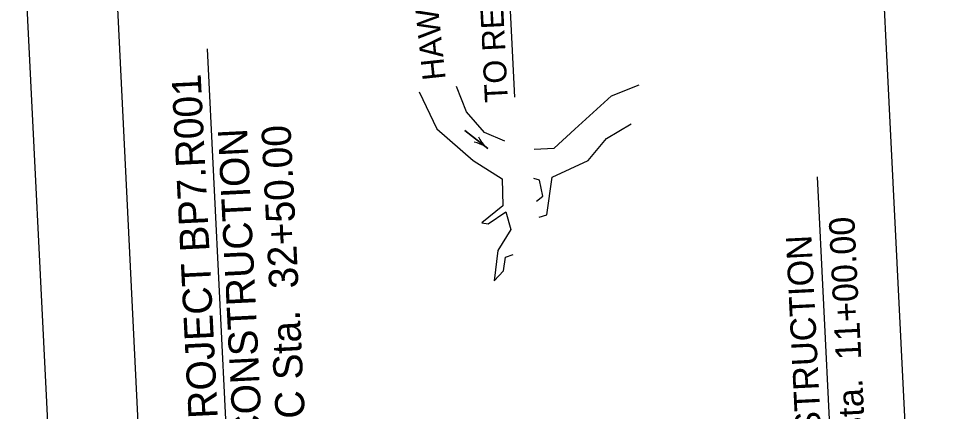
# Model space of a CAD drawing. Extents: x 1805231 to 1809482, y 908883 to 918297.
# Drawn here: x 1807021 to 1808278, y 915762 to 916301 of the extents above; entities that cross this region are included whole.
import ezdxf

# ---------------------------------------------------------------- set-up
doc = ezdxf.new("R2010")
doc.units = 0
for name, color, linetype in [('Default', 7, 'Continuous'), ('Prop Horizontal Alignment Station Label', 7, 'Continuous'), ('Prop Leader Line Medium', 7, 'Continuous'), ('Prop Shade Medium', 7, 'Continuous'), ('Scratch_Level_0', 7, 'Continuous')]:
    doc.layers.add(name, color=color, linetype=linetype)

msp = doc.modelspace()

# ---------------------------------------------------------------- linework, layer by layer
at = {"layer": 'Default'}
for p, q in [((1807833.8, 916195.4), (1807871.6, 916210.3)), ((1807570, 916200.9), (1807594.2, 916150.1)), ((1807635.2, 916173.4), (1807621.5, 916208.2)), ((1807783.6, 916149.6), (1807833.8, 916195.4)), ((1807659.8, 916145.2), (1807635.2, 916173.4)), ((1807594.2, 916150.1), (1807644, 916106.8)), ((1807755, 916123.6), (1807783.6, 916149.6)), ((1807826.9, 916136.6), (1807860.4, 916156.9)), ((1807648.6, 916135.3), (1807648.6, 916135.3)), ((1807687.6, 916132.9), (1807659.8, 916145.2)), ((1807801.8, 916106.5), (1807826.9, 916136.6)), ((1807727.6, 916122.2), (1807755, 916123.6)), ((1807644, 916106.8), (1807683.7, 916081.7)), ((1807752.2, 916083.6), (1807801.8, 916106.5)), ((1807683.7, 916081.7), (1807685, 916044.4)), ((1807735, 916079.8), (1807727.1, 916082.1)), ((1807739.6, 916057.8), (1807735, 916079.8)), ((1807745, 916032.3), (1807752.2, 916083.6)), ((1807730.8, 916050.9), (1807739.6, 916057.8)), ((1807685, 916044.4), (1807655.9, 916021.1)), ((1807664.6, 916019.6), (1807689, 916036.2)), ((1807689, 916036.2), (1807695.6, 916012.2)), ((1807655.9, 916021.1), (1807664.6, 916019.6)), ((1807734.6, 916028.9), (1807745, 916032.3)), ((1807695.6, 916012.2), (1807677.8, 915983.4)), ((1807677.8, 915983.4), (1807673.1, 915941.6)), ((1807685.9, 915955.5), (1807688.6, 915974.3)), ((1807688.6, 915974.3), (1807698.9, 915977.8)), ((1807673.1, 915941.6), (1807685.9, 915955.5))]:
    msp.add_line(p, q, dxfattribs=at)
msp.add_lwpolyline([(1807651.4, 916138.9), (1807653.4, 916135.3), (1807655.7, 916131.9), (1807658.3, 916128.6), (1807661.1, 916125.6), (1807664.3, 916122.9), (1807632.9, 916147.7), (1807664.3, 916122.9), (1807660.9, 916125.4), (1807657.3, 916127.4), (1807653.6, 916129.2), (1807649.7, 916130.6), (1807645.7, 916131.7)], dxfattribs=at)
at = {"layer": 'Prop Horizontal Alignment Station Label'}
for p, q in [((1807279.7, 916259.8), (1807314.8, 915553.5)), ((1808146.3, 915469.5), (1808115.8, 916084.4))]:
    msp.add_line(p, q, dxfattribs=at)
at = {"layer": 'Prop Leader Line Medium'}
msp.add_line((1807681.3, 916586.7), (1807700.8, 916193.6), dxfattribs=at)
at = {"layer": 'Prop Shade Medium'}
msp.add_lwpolyline([(1808257.3, 915314.8), (1808192.5, 916618.4), (1807143.8, 916566.3), (1807143.8, 916566.3), (1807144.4, 916566.4), (1807218.2, 915068.2), (1807212.6, 915181), (1807444, 915192.5)], close=True, dxfattribs=at)
at = {"layer": 'Scratch_Level_0'}
msp.add_lwpolyline([(1807178.4, 913396.6), (1807021.1, 916565.5), (1808571, 916642.5), (1808728.3, 913473.6)], close=True, dxfattribs=at)

# ---------------------------------------------------------------- texts
at = {"layer": 'Prop Horizontal Alignment Station Label'}
for s, height, rotation, p in [('HAW RIVER', 31.5, 96.0539, (1807606.6, 916218.3)), ('END PROJECT BP7.R001', 40, 92.8422, (1807302.4, 915590.5)), ('END CONSTRUCTION', 40, 92.8422, (1807362, 915593.5)), ('-L- POC Sta.  32+50.00', 40, 92.8422, (1807421.6, 915596.4)), ('-RPD- POT Sta.  11+00.00', 35, 92.8422, (1808193.8, 915473.1)), ('BEGIN CONSTRUCTION', 35, 92.8422, (1808133.9, 915470.1))]:
    msp.add_text(s, height=height, rotation=rotation, dxfattribs=at).set_placement(p)
at = {"layer": 'Prop Leader Line Medium'}
msp.add_text('TO REIDSVILLE', height=31.5, rotation=92.8385, dxfattribs=at).set_placement((1807691.8, 916187))

doc.saveas('drawing.dxf')
